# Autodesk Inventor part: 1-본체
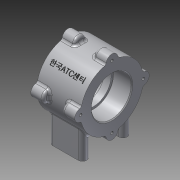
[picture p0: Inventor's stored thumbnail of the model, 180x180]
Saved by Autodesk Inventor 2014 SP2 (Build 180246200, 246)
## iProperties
Created: 2015-03
Part Number: 1-본체
Material: 알루미늄 6061
Document SubType Name: Modeling
Designer: 201-11
Density: 2.71 g/cm^3
Appearance: 알루미늄 - 평지
Mass: 450.84 g
Surface Area: 333.946 cm^2
Volume: 166.362 cm^3
Author: 201-11
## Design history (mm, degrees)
sketch "스케치1"
  geometry: C1 r 37 at (0, 0); 1 further point
  constraints: 1 centre point, 1 coincident
  dimensions: "d0" = 74 diameter of C1
extrude "돌출1" new body sketch "스케치1" stored distance "d1" = 52; taper "d2" = 0 deg
sketch "스케치2"
  geometry: L1 (-37, 0)-(0, 0); A1 r 37 centre (0, 0) between (-37, 0) and (-36.338, 6.969) reference; A2 r 7 centre (-37, 0) between (-36.338, 6.969) and (-36.338, -6.969); 1 further point
  constraints: 5 point on circle, 2 end point, 1 centre point, 1 horizontal
  dimensions: "d3" = 14 diameter of A2
extrude "돌출2" join sketch "스케치2" distance "d4" = 15; taper "d5" = 0 deg
fillet "모깎기1" dims "d6" = 3
fillet "모깎기2" dims "d7" = 3
hole "구멍1" diameter "d13" = 47; stored, may be unused: countersink angle "d17" = 90 deg, drill point angle "d19" = 0 deg; dims "d11" = 10, "d12" = 10, "d14" = 6, "d15" = 4, "d16" = 2, "d18" = 22
hole "구멍2" diameter "d22" = 47; stored, may be unused: countersink angle "d26" = 90 deg, drill point angle "d28" = 0 deg; dims "d20" = 10, "d21" = 10, "d23" = 6, "d24" = 4, "d25" = 2, "d27" = 22
hole "구멍3" diameter "d31" = 42; stored, may be unused: countersink angle "d35" = 90 deg, drill point angle "d37" = 0 deg; dims "d29" = 10, "d30" = 10, "d32" = 6, "d33" = 4, "d34" = 2, "d36" = 22
hole "구멍4" diameter "d40" = 3.242; stored, may be unused: countersink angle "d44" = 90 deg, drill point angle "d46" = 118 deg; dims "d38" = 10, "d39" = 10, "d41" = 8, "d42" = 4, "d43" = 2, "d45" = 11
sketch "스케치3" dims "d24" = 4
  geometry: L1 (-29, -22.978)-(-29, -56); L2 (-29, -56)-(-19, -56); L3 (-19, -56)-(-19, -31.749); L4 (-24, -56)-(-24, -30); C1 r 21 at (0, 0) reference; A1 r 37 centre (0, 0) between (-29, -22.978) and (-19, -31.749) reference; 1 further point
  constraints: 8 end point, 2 point on circle, 1 midpoint, 1 parallel, 1 perpendicular, 1 vertical
  dimensions: "d50" = 56 distance from line of L2 point (0, 0); "d51" = 10 distance between parallel lines of L3 L1; "d52" = 26 distance of L4.start L4.end; "d53" = 90 deg angle of L2 L4; "d54" = 24 distance from line of point (0, 0) L4
extrude "돌출3" join sketch "스케치3" stored distance "d55" = 40; taper "d56" = 0 deg
fillet "모깎기3" dims "d57" = 5
fillet "모깎기4" dims "d58" = 3
hole "구멍5" diameter "d61" = 4.134; stored, may be unused: countersink angle "d65" = 90 deg, drill point angle "d67" = 118 deg; dims "d59" = 10, "d60" = 10, "d62" = 6, "d63" = 4, "d64" = 2, "d66" = 8
chamfer "모따기1" distance "d71" = 1; stored, may be unused: second distance "d72" = 2, angle "d73" = 45 deg
fillet "모깎기5" dims "d74" = 0.3
sketch "스케치4"
  geometry: L1 (0, 0)-(0, 37); L2 (0, 0)-(-26.163, 26.163); A1 r 7 centre (0, 37) between (6.889, 38.239) and (-6.889, 38.239) reference; A2 r 37 centre (0, 0) between (-9.104, 35.863) and (-35.863, 9.104) reference
  constraints: 4 end point, 1 point on circle, 1 vertical
  dimensions: "d75" = 45 deg angle of L1 L2
node "작업 평면1"
sketch "스케치5"
  geometry: L1 (-46.739, 3.002)-(-5.261, 3.002); L2 (-5.261, 3.002)-(-5.261, -3.002); L3 (-5.261, -3.002)-(-46.739, -3.002); L4 (-46.739, -3.002)-(-46.739, 3.002); L5 (-46.739, 0)-(-5.261, 0); L6 (-26, 3.002)-(-26, -3.002); L7 (-52, 18.921)-(-52, -18.921) reference; 1 further point
  constraints: 4 end point, 4 midpoint, 2 other
  dimensions: "d76" = 6.00407 distance of L6.start L6.end; "d77" = 41.47897 distance of L5.start L5.end; "d78" = 26 distance between parallel lines of L7 L6; "d79" = 0 distance from line of point (-26, 0) L5
feature "엠보싱1" sketch "스케치5" dims "d8" = 40, "d80" = 0.5, "d81" = 0
node "솔리드1"
pattern_circular "원형 패턴1" dims "d9" = 360 deg
mirror "대칭1"
pattern_circular "원형 패턴2" dims angle "d48" = 360 deg
mirror "대칭2"
pattern_linear "직사각형 패턴1" dims "d70" = 30
mirror "대칭3"
node "절단 모서리 투영1"
